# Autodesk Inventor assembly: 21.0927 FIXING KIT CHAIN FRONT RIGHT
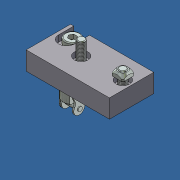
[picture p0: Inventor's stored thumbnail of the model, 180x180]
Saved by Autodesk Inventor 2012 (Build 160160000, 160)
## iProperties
Created: 2013-11
Part Number: 21.0927 FIXING KIT CHAIN FRONT RIGHT
Document SubType Name: Assembly
Designer: Admin
Description: FIXING KIT CHAIN FRONT
Author: Admin
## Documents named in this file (8)
- C:\Andys Backup Data\ANDY'S INVENTOR\INVENTOR LIBRARIES\PARTS LIBRARY\COUNTER WEIGHT SYSTEM HEAVY\21.0927 FIXING KIT CHAIN FRONT RIGHT.iam
- C:\Andys Backup Data\ANDY'S INVENTOR\INVENTOR LIBRARIES\PARTS LIBRARY\COUNTER WEIGHT SYSTEM HEAVY\SUBCOMPONENTS\21.0927 FIXING KIT FOR CHAIN FRONT.ipt
- C:\Andys Backup Data\ANDY'S INVENTOR\INVENTOR LIBRARIES\PARTS LIBRARY\COUNTER WEIGHT SYSTEM HEAVY\SUBCOMPONENTS\21.0925 CHAIN CLAMPING DEVICE S.ipt
- C:\Andys Backup Data\ANDY'S INVENTOR\INVENTOR LIBRARIES\PARTS LIBRARY\COUNTER WEIGHT SYSTEM HEAVY\29.0308 CONNECTING LINK 08B.iam
- C:\Andys Backup Data\ANDY'S INVENTOR\INVENTOR LIBRARIES\PARTS LIBRARY\FASTENING ELEMENTS\SCREWS CAP\21.1249 M10X25.ipt
- C:\Andys Backup Data\ANDY'S INVENTOR\INVENTOR LIBRARIES\PARTS LIBRARY\FASTENING ELEMENTS\SCREWS CAP\21.1204 M8X25.ipt
- C:\Andys Backup Data\ANDY'S INVENTOR\INVENTOR LIBRARIES\PARTS LIBRARY\FASTENING ELEMENTS\SCREWS CAP\21.1206 M8X30.ipt
- C:\Andys Backup Data\ANDY'S INVENTOR\INVENTOR LIBRARIES\PARTS LIBRARY\FASTENING ELEMENTS\NUTS\21.1351 M8 SQUARE NUT.ipt
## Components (7 placed, 7 different names)
1. 21.0927 FIXING KIT FOR CHAIN FRONT:1 — Insert:1, Insert:2, Angle:1, Insert:3, Insert:4, Angle:2, Insert:5, Angle:3
2. 21.0925 CHAIN CLAMPING DEVICE S:2 — Insert:2, Angle:1, Mate:1, Mate:2
3. 29.0308 CONNECTING LINK 08B:2 [sub-assembly] — Mate:1, Mate:2, Angle:2
4. 21.1206 M8 x 30:2 — Insert:3
5. 21.1204  M8 x 25:3 — Insert:4
6. 21.1249 M10 X 25:2 — Insert:1
7. 21.1351 M8 SQUARE NUT:2 — Insert:5, Angle:3
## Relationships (10: Insert 5, Angle 3, Mate 2)
- Insert:1: 21.0927 FIXING KIT FOR CHAIN FRONT:1 ↔ 21.1249 M10 X 25:2
- Insert:2: 21.0927 FIXING KIT FOR CHAIN FRONT:1 ↔ 21.0925 CHAIN CLAMPING DEVICE S:2
- Angle:1: 21.0927 FIXING KIT FOR CHAIN FRONT:1 ↔ 21.0925 CHAIN CLAMPING DEVICE S:2
- Insert:3: 21.0927 FIXING KIT FOR CHAIN FRONT:1 ↔ 21.1206 M8 x 30:2
- Insert:4: 21.0927 FIXING KIT FOR CHAIN FRONT:1 ↔ 21.1204  M8 x 25:3
- Mate:1: 21.0925 CHAIN CLAMPING DEVICE S:2 ↔ 29.0308 CONNECTING LINK 08B:2
- Mate:2: 21.0925 CHAIN CLAMPING DEVICE S:2 ↔ 29.0308 CONNECTING LINK 08B:2
- Angle:2: 21.0927 FIXING KIT FOR CHAIN FRONT:1 ↔ 29.0308 CONNECTING LINK 08B:2
- Insert:5: 21.0927 FIXING KIT FOR CHAIN FRONT:1 ↔ 21.1351 M8 SQUARE NUT:2
- Angle:3: 21.0927 FIXING KIT FOR CHAIN FRONT:1 ↔ 21.1351 M8 SQUARE NUT:2
